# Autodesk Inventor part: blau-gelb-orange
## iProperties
Created: 2004-10
Part Number: blau-gelb-orange
Document SubType Name: Modeling
Designer: sahrens
Manufacturer: Standard
Standards Organization: Custom
Author: sahrens
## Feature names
1. Extrusion1
2. Rundung2 [Fillet]
